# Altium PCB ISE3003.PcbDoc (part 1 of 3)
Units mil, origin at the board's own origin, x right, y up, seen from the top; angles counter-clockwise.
Board outline 3937.01 x 3937.01 mil, 2 copper layers (Top Layer, Bottom Layer), stack 62 mil thick; 230 components, 119 nets, 522 pads, 174 vias.
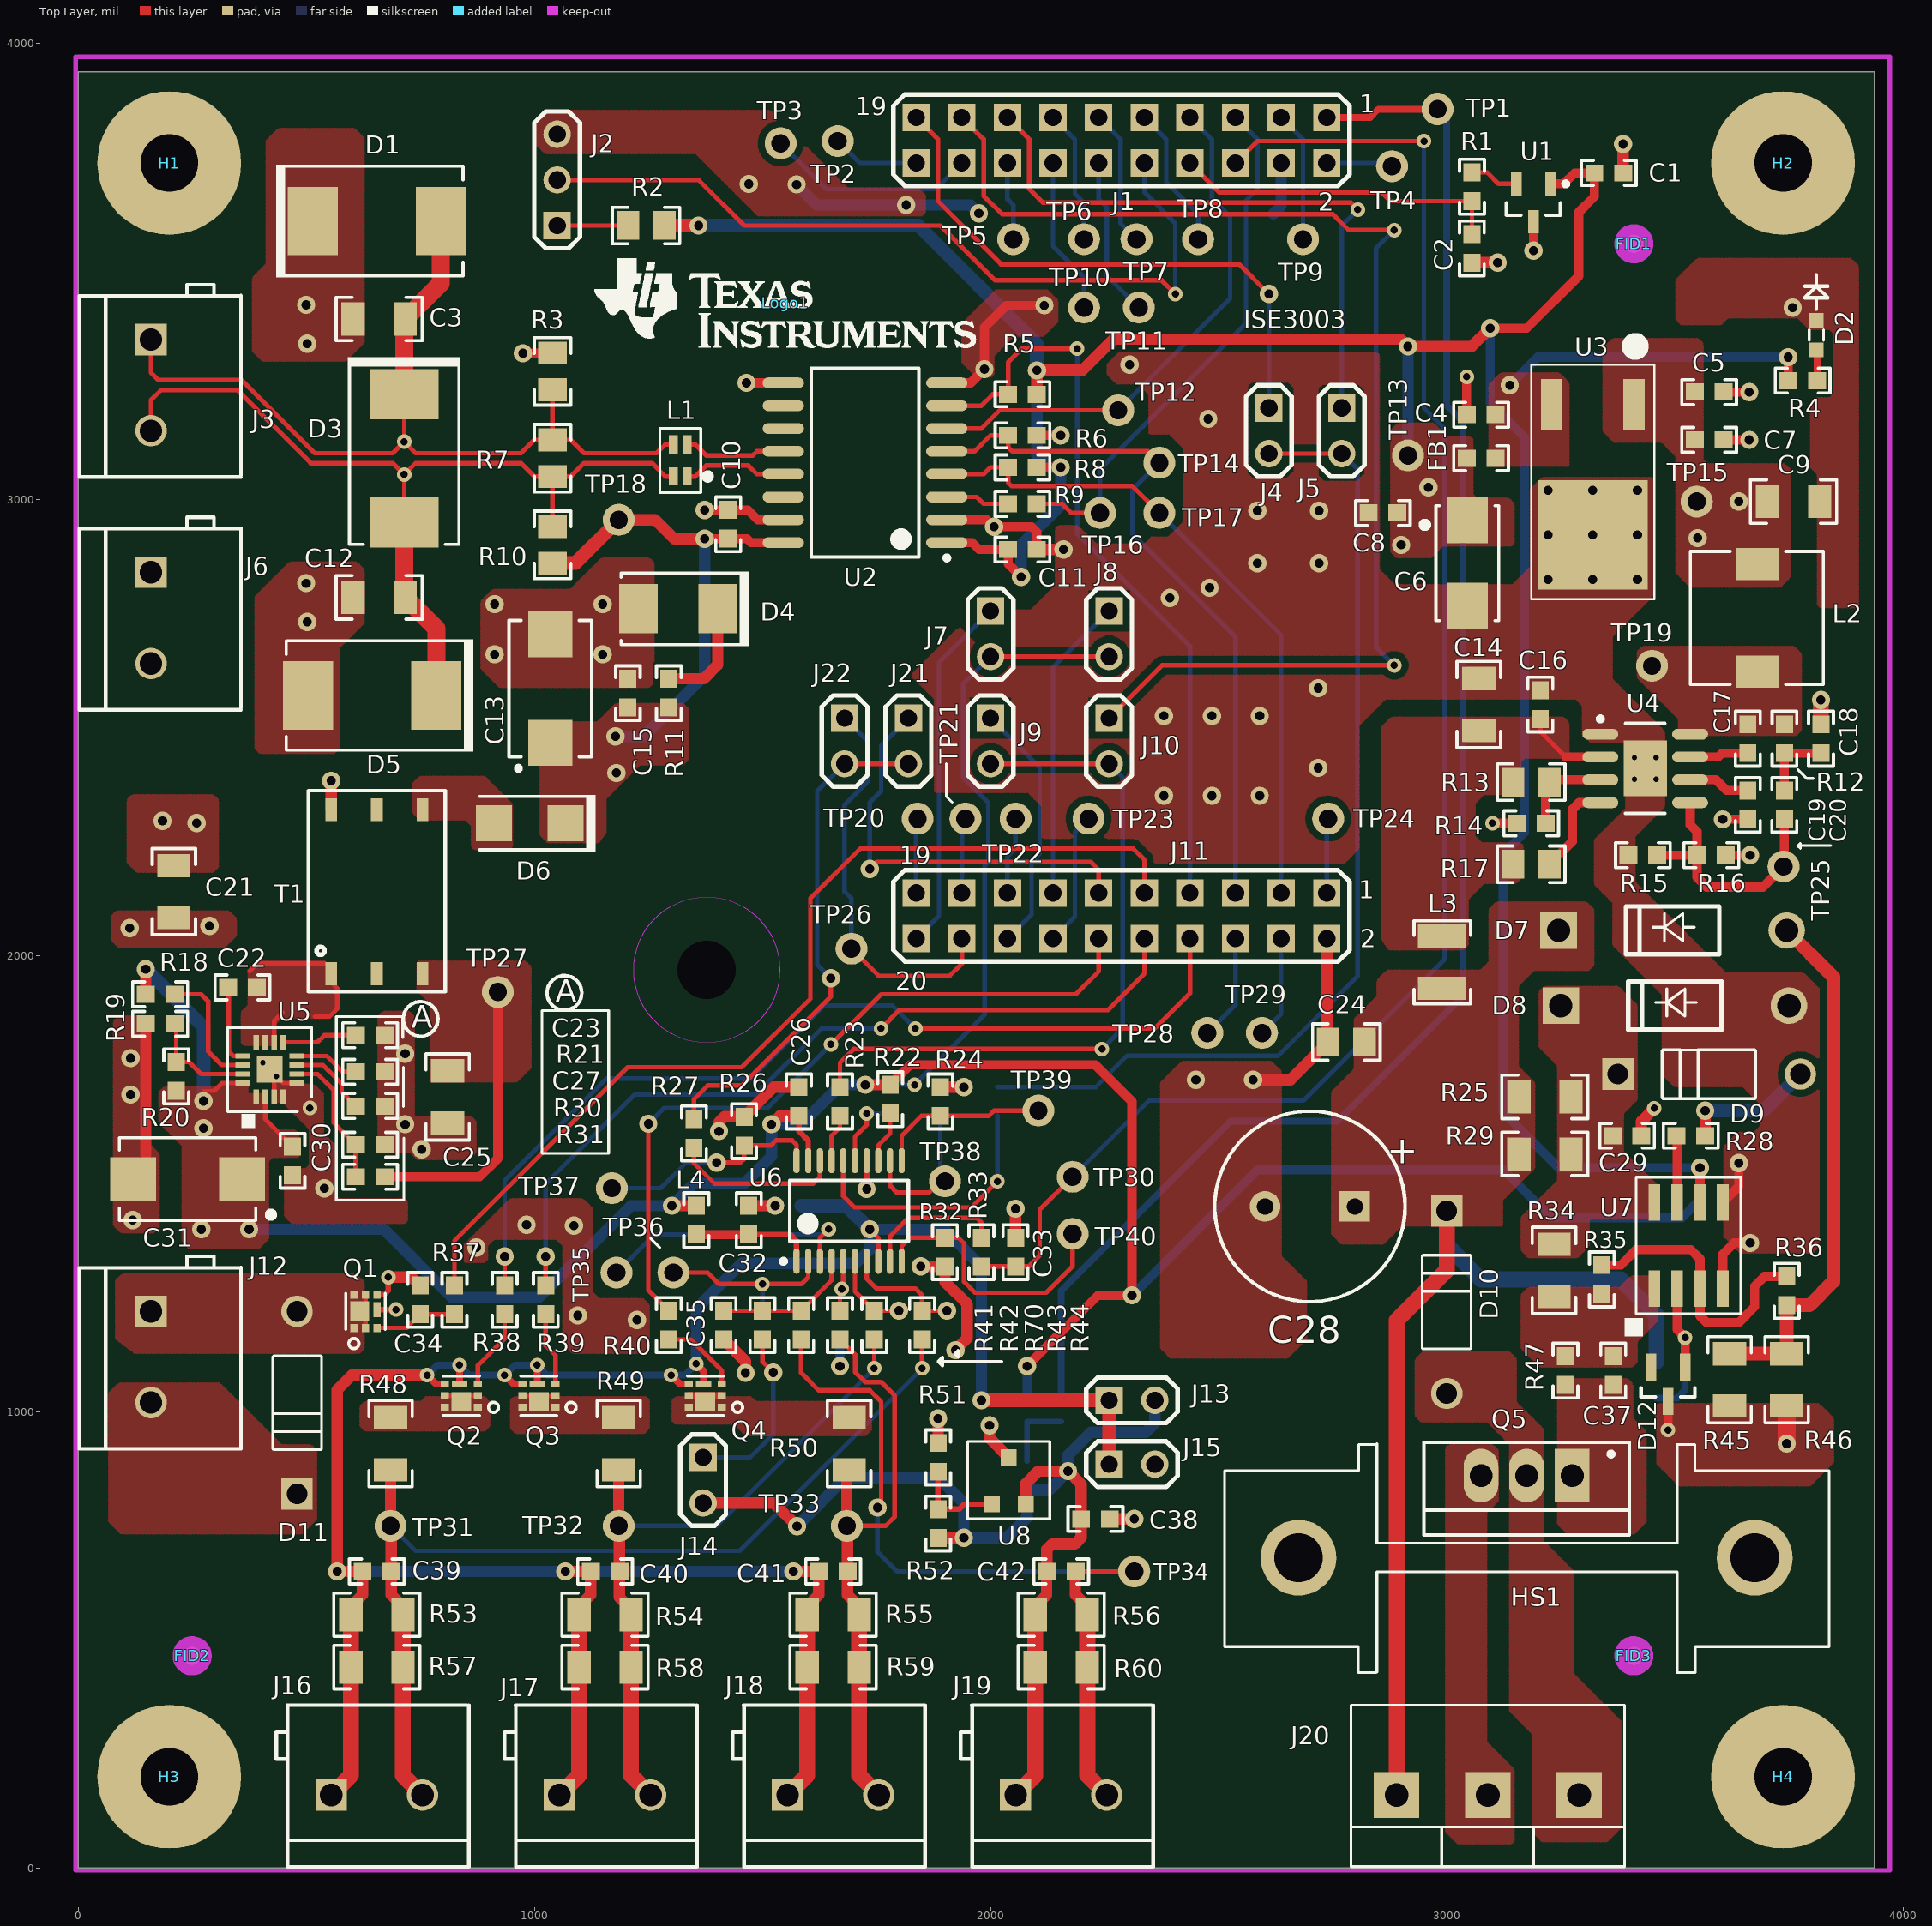
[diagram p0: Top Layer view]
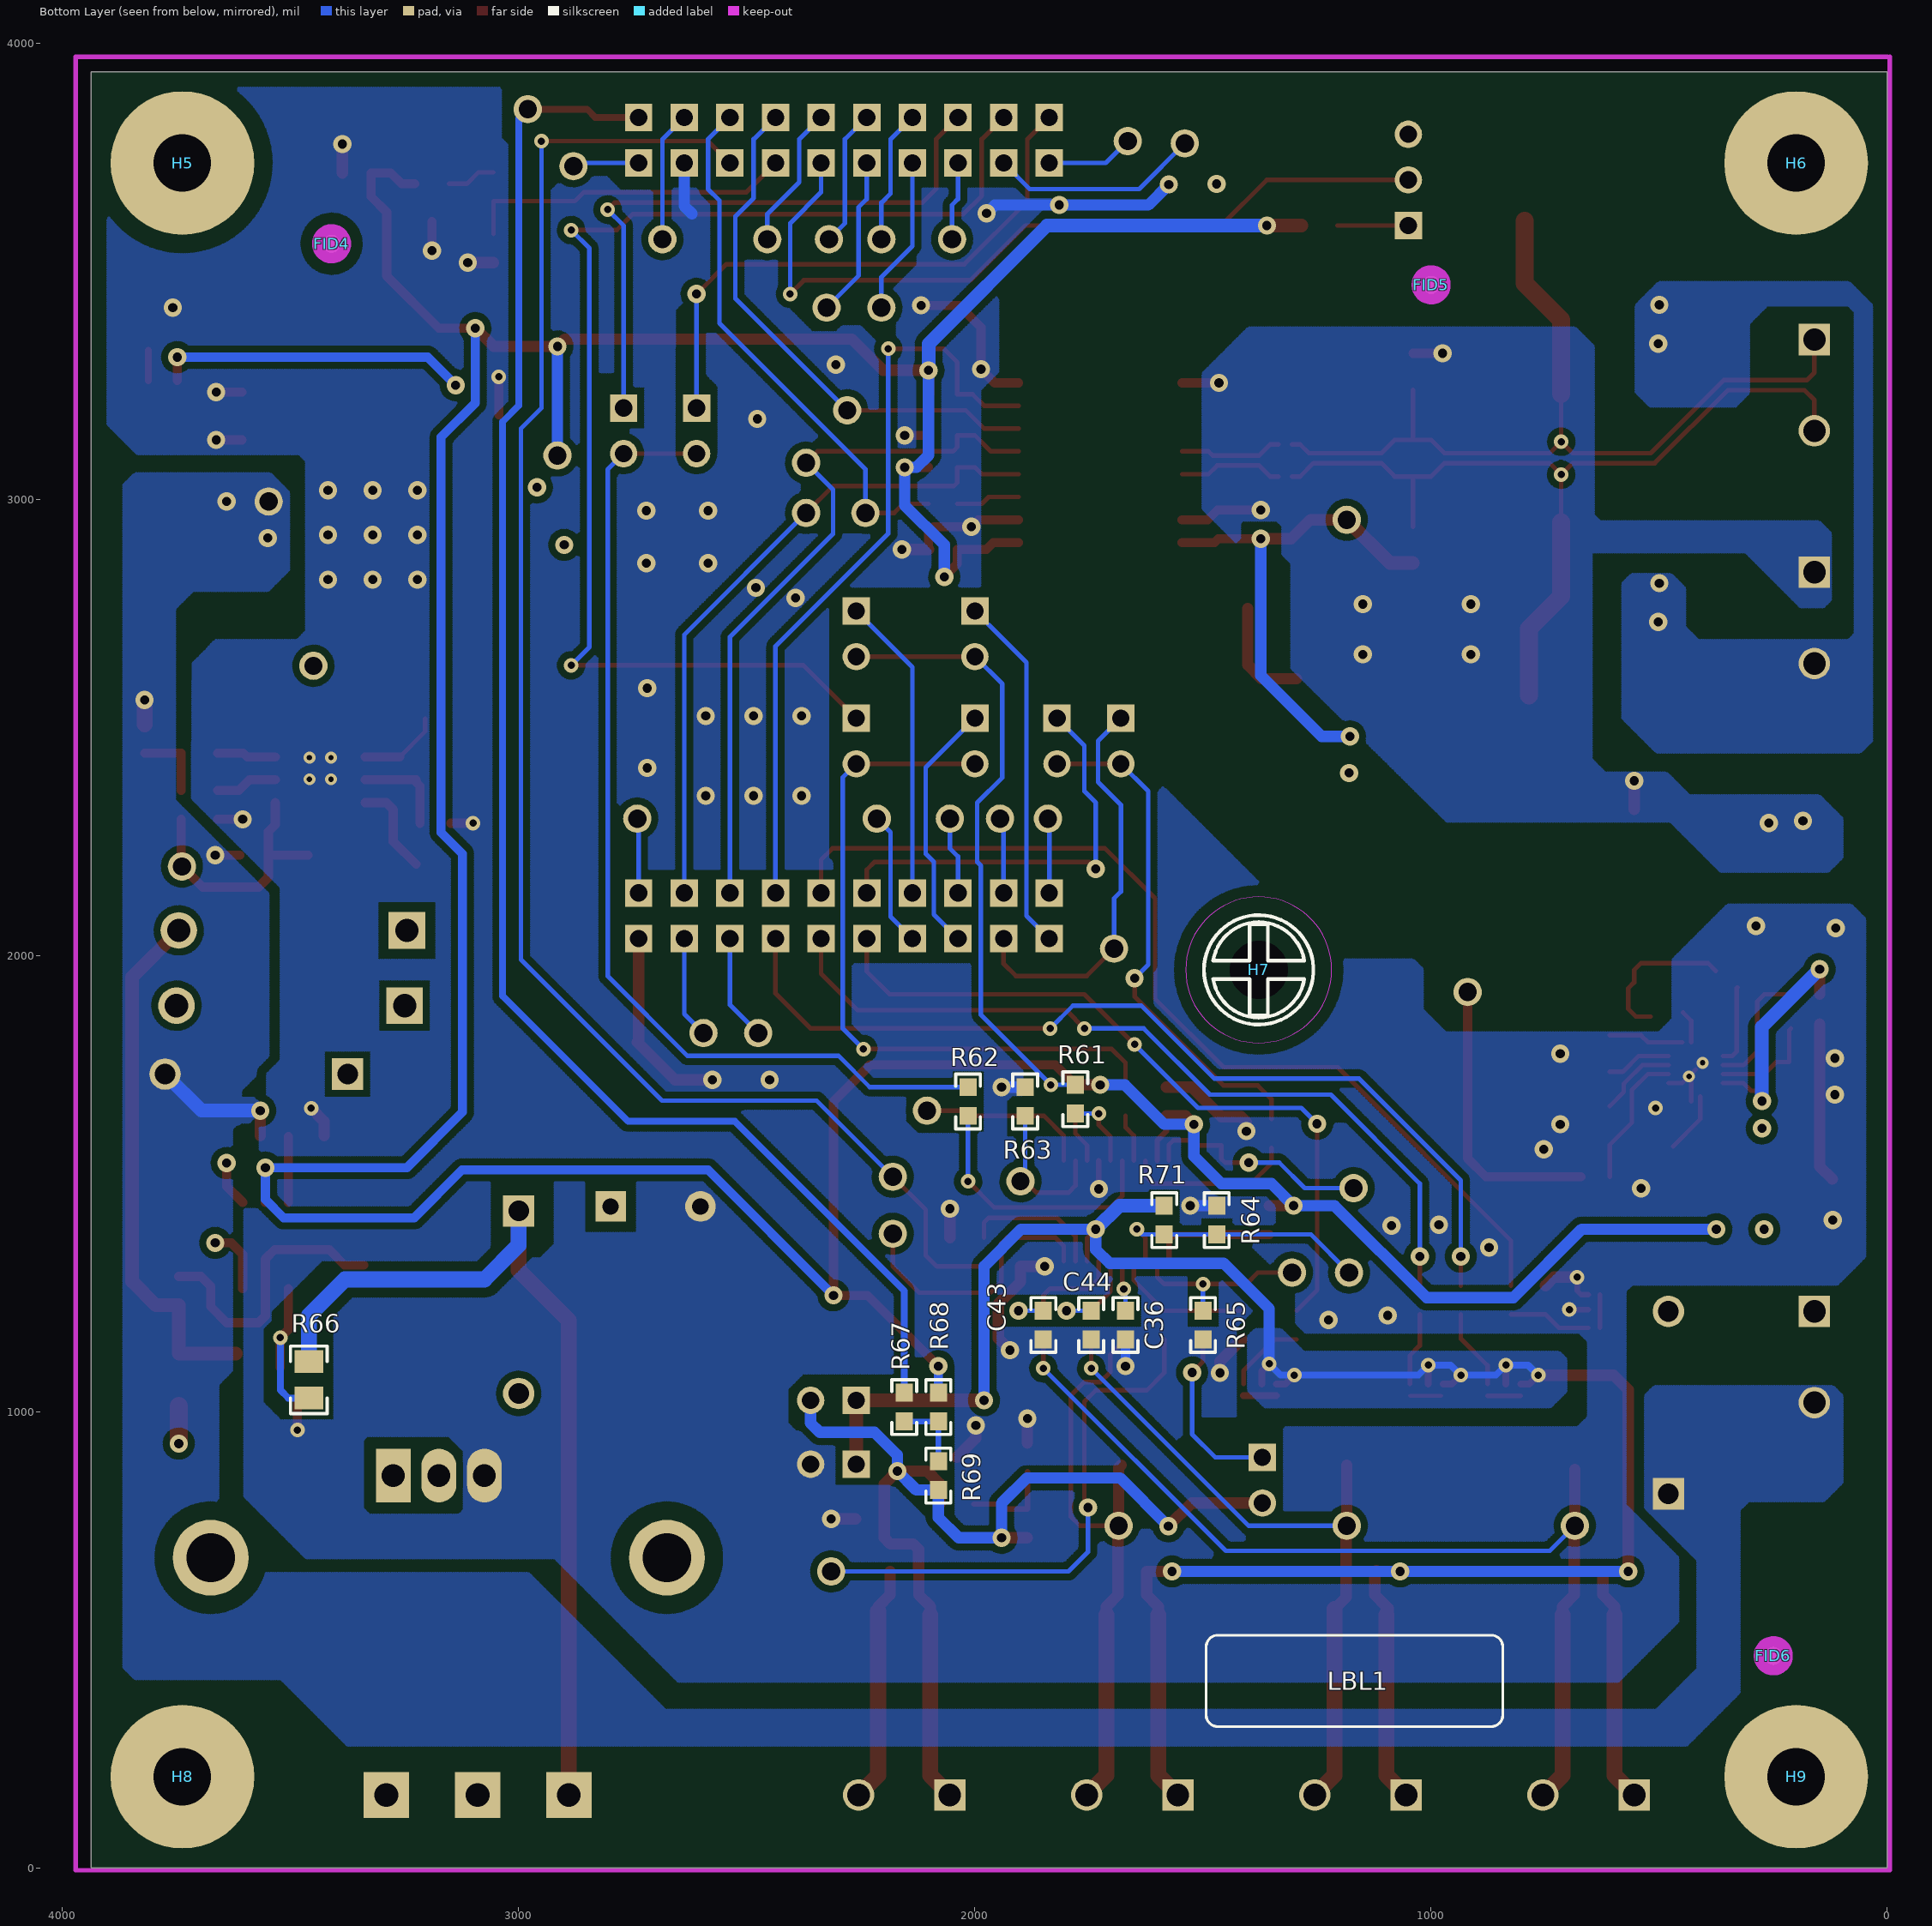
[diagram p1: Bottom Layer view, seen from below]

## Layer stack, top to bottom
Top Layer: signal copper 1.4
Dielectric: core 59.2, FR-4, Dk 4.8
Bottom Layer: signal copper 1.4

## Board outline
0,0 0,3937.01 3937.01,3937.01 3937.01,0

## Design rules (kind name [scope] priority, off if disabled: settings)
AcuteAngle [All] p1: minimum=4.50000000000000E+0001 checktracksonly=FALSE
AssemblyTestPointUsage [All] p1: valid=2
Clearance Clearance_MTG [InPadClass('MTG') vs InPolygon] p1: gap=40
Clearance Clearance_39V [InNet('39V')] p2: gap=22
Clearance Clearance_THPIN [IsVia vs IsThruPin] p3: gap=12
Clearance "Clearance_PAD Class" [InPadClass('PADClass') vs InPadClass('PADClass')] p4: gap=7.9
Clearance "Via to Via" [IsVia vs IsVia] p5: gap=12
Clearance "Via to SMT PIN" [IsVia vs IsSMTPin] p6: gap=12
Clearance "Clearance_Poly to Poly" [InPolygon vs InPolygon] p7: gap=20
Clearance Clearance_BoardEdge_MountingHoles [OnCopper and InComponentClass('Mounting Holes') vs IsKeepOut] p8: gap=40
Clearance Clearance_BoardEdge_Poly [OnCopper and InPoly vs IsKeepOut] p9: gap=25
Clearance Clearance_BoardEdge [OnCopper and Not InComponentClass('Logo') and not InComponentClass('FiducialMark') and not InRegion(1000,500,4000,800) and Not IsKeepout vs IsKeepOut] p10: gap=40
Clearance Clearance_Poly [InPolygon] p11: gap=15
Clearance [All] p12: gap=8
ComponentClearance ComponentClearance_Logo [InComponentClass('Logo')] p1: gap=50 collisioncheckmode=3 verticalgap=10 showdistances=FALSE
ComponentClearance ComponentClearance_ScrewToNut [(HasFootprint('NY PMS 440 0025 PH')) vs (HasFootprint('Keystone_1902C'))] p2: gap=5 collisioncheckmode=3 verticalgap=10 showdistances=FALSE
ComponentClearance ComponentClearance_MountingHoles [InComponentClass('Mounting Holes')] p3: gap=250 collisioncheckmode=3 verticalgap=100000 showdistances=FALSE
ComponentClearance ComponentClearance_SmallPassives [HasFootprint('0201*') or HasFootprint('0402*') or HasFootprint('0508') or HasFootprint('0603*') or HasFootprint('0612') or HasFootprint('0805*') or HasFootprint('0815*') or HasFootprint('0830*') or HasFootprint('1206*') or HasFootprint('1210*') or HasFootprint('1808*') or HasFootprint('1812*') or HasFootprint('1825*') or HasFootprint('2010*') or HasFootprint('2220*') or HasFootprint('2225*') or HasFootprint('2512*') or HasFootprint('2728*') or HasFootprint('3518*') vs HasFootprint('0201*') or HasFootprint('0402*') or HasFootprint('0508') or HasFootprint('0603*') or HasFootprint('0612') or HasFootprint('0805*') or HasFootprint('0815*') or HasFootprint('0830*') or HasFootprint('1206*') or HasFootprint('1210*') or HasFootprint('1808*') or HasFootprint('1812*') or HasFootprint('1825*') or HasFootprint('2010*') or HasFootprint('2220*') or HasFootprint('2225*') or HasFootprint('2512*') or HasFootprint('2728*') or HasFootprint('3518*')] p4: gap=20 collisioncheckmode=3 verticalgap=10 showdistances=FALSE
ComponentClearance ComponentClearance_THtoSMT [IsThruComponent vs IsSMTComponent] p5: gap=100 collisioncheckmode=3 verticalgap=30 showdistances=FALSE
ComponentClearance ComponentClearance_THtoTH [IsThruComponent vs IsThruComponent] p6: gap=118.11 collisioncheckmode=3 verticalgap=30 showdistances=FALSE
ComponentClearance [All] p7: gap=40 collisioncheckmode=3 verticalgap=10 showdistances=FALSE
DiffPairsRouting DiffPair_DiffPairsRouting [InDifferentialPair ('RS485_2')] p1: maxlimit=12 minlimit=12 mostfreqgap=12 maxuncoupledlength=500
DiffPairsRouting DiffPair_RS485DiffPairsRouting [InDifferentialPair ('NewDifferentialPair1')] p2: maxlimit=12 minlimit=12 mostfreqgap=12 maxuncoupledlength=500
DiffPairsRouting DiffPair_RS485_2DiffPairsRouting [InDifferentialPair ('RS485_2')] p3: maxlimit=12 minlimit=12 mostfreqgap=12 maxuncoupledlength=500
DiffPairsRouting DiffPair_RS485_1DiffPairsRouting [InDifferentialPair ('RS485_1')] p4: maxlimit=12 minlimit=12 mostfreqgap=12 maxuncoupledlength=500
DiffPairsRouting [All] p5: maxlimit=100 minlimit=10 mostfreqgap=10 maxuncoupledlength=1000
FabricationTestPointUsage TestPointUsage [All] p1: valid=2 allowmultiple=FALSE
FabricationTestpoint Testpoint [All] p1: side=3 testpointundercomponent=TRUE minsize=40 maxsize=100 preferedsize=60 minholesize=0 maxholesize=40 preferedholesize=32 testpointgrid=1 allowsidetop=TRUE allowsidebottom=TRUE usegrid=TRUE gridtolerance=0.01
FanoutControl Fanout_LCC [IsLCC] p1: bgadir=Out bgaviamode=Centered fanoutstyle=Auto fanoutdirection=Alternating viagrid=1 // Fanout_LCC (Default Rule)
FanoutControl Fanout_BGA [IsBGA] p2: bgadir=Out bgaviamode=Centered fanoutstyle=Auto fanoutdirection=Alternating viagrid=1 // Fanout_BGA (Default Rule)
FanoutControl Fanout_Default [All] p4: bgadir=Out bgaviamode=Centered fanoutstyle=Auto fanoutdirection=Alternating viagrid=1 // Fanout_Default (Default Rule)
FanoutControl Fanout_Small [(CompPinCount < 5)] p5: bgadir=Out bgaviamode=Centered fanoutstyle=Auto fanoutdirection=OutThenIn viagrid=1 // Fanout_Small (Default Rule)
HoleSize [All] p1: absolutevalues=TRUE maxlimit=251 minlimit=8 maxpercent=80.000 minpercent=20.000
MatchedLengths DiffPair_MatchedLengths [InDifferentialPair ('RS485_2')] p1: tolerance=1000 checknetsindiffpair=TRUE checkdiffpairvsdiffpair=TRUE checkothers=TRUE
MatchedLengths DiffPair_RS485MatchedLengths [InDifferentialPair ('NewDifferentialPair1')] p2: tolerance=1000 checknetsindiffpair=TRUE checkdiffpairvsdiffpair=TRUE checkothers=TRUE
MatchedLengths DiffPair_RS485_2MatchedLengths [InDifferentialPair ('RS485_2')] p3: tolerance=1000 checknetsindiffpair=TRUE checkdiffpairvsdiffpair=TRUE checkothers=TRUE
MatchedLengths DiffPair_RS485_1MatchedLengths [InDifferentialPair ('RS485_1')] p4: tolerance=1000 checknetsindiffpair=TRUE checkdiffpairvsdiffpair=TRUE checkothers=TRUE
MinimumAnnularRing MinimumAnnularRing_ThermalPadVias [IsVia and InAnyComponent] p1: minimumring=5.91
MinimumAnnularRing [All] p2: minimumring=7
MinimumSolderMaskSliver MinimumSolderMaskSliver_Logo [InComponentClass('Logo') vs InComponentClass('Logo')] p1: minsoldermaskwidth=0.7
MinimumSolderMaskSliver [All] p2: minsoldermaskwidth=3.94
PlaneConnect [All] p1: planeconnectstyle=Relief reliefexpansion=10 reliefentries=4 reliefconductorwidth=10 reliefairgap=10
PolygonConnect PolygonConnect_All [All] p1: connectstyle=Direct reliefconductorwidth=10 reliefentries=4 polygonreliefangle="90 Angle" airgapwidth=10
RoutingVias ThermalPadVias [IsVia and InAnyComponent] p1: holewidth=7.87 width=19.68 viastyle="Through Hole" minholewidth=7.87 minwidth=19.68 maxholewidth=12 maxwidth=26
RoutingVias [All] p2: holewidth=16 width=32 viastyle="Through Hole" minholewidth=12 minwidth=26 maxholewidth=20 maxwidth=40
SMDToCorner [All] p1: distance=30000
SilkToSilkClearance [All] p1: silktosilkclearance=5
SilkscreenOverComponentPads [All] p1: minsilkscreentomaskgap=5
SolderMaskExpansion [All] p1: expansion=2
Width DiffPair_Width [InDifferentialPair('RS485_2')] p1: maxlimit=10 minlimit=10 preferedwidth=10
Width DiffPair_RS485Width [InDifferentialPair('NewDifferentialPair1')] p2: maxlimit=200 minlimit=10 preferedwidth=10
Width DiffPair_RS485_2Width [InDifferentialPair('RS485_2')] p3: maxlimit=100 minlimit=10 preferedwidth=10
Width DiffPair_RS485_1Width [InDifferentialPair('RS485_1')] p4: maxlimit=100 minlimit=10 preferedwidth=10
Width Width_RS485 [InNetClass('RS485')] p5: maxlimit=100 minlimit=10 preferedwidth=10
Width [All] p6: maxlimit=100 minlimit=6 preferedwidth=10 checkconnectedcopper=TRUE
14 further rules are at their usual default settings.

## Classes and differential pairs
pad class MTG: H1-1 H2-1 H3-1 H4-1 HS1-1 HS1-2
component class "Mounting Holes": H1 H2 H3 H4
component class Logo: Logo1
component class "Pg7 Hardware": FID1 FID2 FID3 FID4 FID5 FID6 H1 H2 H3 H4 H5 H6 H7 H8 H9 LBL1 Logo1 ZZ1 ZZ2 ZZ3 ZZ4
component class FiducialMark: FID1 FID2 FID3 FID4 FID5 FID6
component class AssemblyNote: ZZ1 ZZ2 ZZ3 ZZ4
component class Label: LBL1
component class Pg3: C4 C5 C6 C7 C8 C9 C14 C16 C17 C18 C19 C20 C24 C28 C29 C34 C37 D2 D7 D8 D9 D10 D11 D12 FB1 HS1 J12 J20 L2 L3 Q1 Q5 R4 R12 R13 R14 R15 R16 R17 R25 R28 R29 R34 R35 R36 R37 R45 R46 R47 R66 TP13 TP15 TP19 TP25 U3 U4 U7
component class Pg4: C1 C2 C26 C32 C33 C35 C36 C38 C39 C40 C41 C42 C43 C44 J13 J14 J15 J16 J17 J18 J19 L4 Q2 Q3 Q4 R1 R22 R23 R24 R26 R27 R32 R33 R38 R39 R40 R41 R42 R43 R44 R48 R49 R50 R51 R52 R53 R54 R55 R56 R57 R58 R59 R60 R61 R62 R63 R64 R65 R67 R68 R69 R70 R71 TP30 TP31 TP32 TP33 TP34 TP35 TP36 TP37 TP38 TP39 TP40 U1 U6 U8
component class Pg5: C3 C10 C11 C12 C13 C15 C21 C22 C23 C25 C27 C30 C31 D1 D3 D4 D5 D6 J3 J6 L1 R3 R5 R6 R7 R8 R9 R10 R11 R18 R19 R20 R21 R30 R31 T1 TP12 TP14 TP16 TP17 TP18 TP27 U2 U5
component class Pg6: J1 J2 J4 J5 J7 J8 J9 J10 J11 J21 J22 R2 TP1 TP2 TP3 TP4 TP5 TP6 TP7 TP8 TP9 TP10 TP11 TP20 TP21 TP22 TP23 TP24 TP26 TP28 TP29
pad class PADClass: U5-1 U5-2 U5-3 U5-4 U5-5 U5-6 U5-7 U5-8 U5-9 U5-10 U5-11 U5-12 U5-13 U5-14 U5-15 U5-16
differential pair RS485_2: +NetL1_2 -NetL1_1
differential pair RS485_1: +RS485_ISO_A -RS485_ISO_B

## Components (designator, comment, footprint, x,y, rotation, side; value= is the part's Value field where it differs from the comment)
C1 "06033C104JAT2A" 0603 3355,3715 r0 top (schematic designator C47)
C2 "06033C104JAT2A" 0603 3055,3550 r90 top (schematic designator C17)
C3 "CC1206KKX7RCBB102" 1206 660,3395 r180 top (schematic designator C32)
C4 "C1608X7R1C105K" 0603 3075,3185 r180 top (schematic designator C13)
C5 "C0603C104K5RACTU" 0603 3575,3235 r0 top (schematic designator C15)
C6 "293D475X9035C2TE3" 6032-28 3045,2860 r270 top (schematic designator C11)
C7 "C1608X7R1C105K" 0603 3575,3130 r0 top (schematic designator C14)
C8 "C0603C104K5RACTU" 0603 2860,2970 r180 top (schematic designator C12)
C9 "GRM31CR61C226KE15L" 1206 3760,2995 r0 top (schematic designator C8)
C10 "06033C104JAT2A" 0603 1425,2945 r270 top (schematic designator C30)
C11 "06033C104JAT2A" 0603 2070,2890 r180 top (schematic designator C29)
C12 "CC1206KKX7RCBB102" 1206 660,2785 r0 top (schematic designator C31)
C13 "T495X476K035ATE300" 7343-43 1035,2585 r90 top (schematic designator C38)
C14 "GRM31CR72A105KA01L" 1206 3070,2550 r270 top (schematic designator C1)
C15 "06033C104JAT2A" 0603 1205,2575 r90 top (schematic designator C39)
C16 "06033C104JAT2A" 0603 3205,2550 r90 top (schematic designator C2)
C17 "C1608C0G1E103J" 0603 3660,2475 r90 top (schematic designator C6)
C18 "C0603C332K5RACTU" 0603 3820,2475 r270 top (schematic designator C7)
C19 "C1608X5R1E105K080AC" 0603 3660,2330 r270 top (schematic designator C10)
C20 "06033C104JAT2A" 0603 3740,2330 r90 top (schematic designator C9)
C21 "CC1206KKX7RCBB102" 1206 210,2140 r270 top (schematic designator C36)
C22 "06033C104JAT2A" 0603 360,1930 r180 top (schematic designator C33)
C23 "06033C104JAT2A" 0603 640,1825 r180 top (schematic designator C37)
C24 "C0805C104K1RACTU" 0805_HV 2780,1810 r180 top (schematic designator C4)
C25 "1206YD226MAT2A" 1206 810,1690 r270 top (schematic designator C41)
C26 "06033C104JAT2A" 0603 1580,1680 r270 top (schematic designator C19)
C27 "C1608C0G1E103J" 0603 640,1670 r0 top (schematic designator C40)
C28 "100YXJ100M10X20" YXJ_1000x2000 2700,1450 r180 top locked (schematic designator C3)
C29 "C0603C104K5RACTU" 0603 3395,1605 r0 top (schematic designator C45)
C30 "06033C104JAT2A" 0603 470,1550 r270 top (schematic designator C35)
C31 "T495X476K035ATE300" 7343-43 240,1510 r180 top (schematic designator C34)
C32 "06033C104JAT2A" 0603 1470,1420 r270 top (schematic designator C20)
C33 "C1608C0G1E103J" 0603 2055,1350 r90 top (schematic designator C27)
C34 "06033C104JAT2A" 0603 750,1245 r90 top (schematic designator C16)
C35 "C1608C0G1E103J" 0603 1415,1190 r270 top (schematic designator C23)
C36 "C1608C0G1E103J" 0603 1670,1190 r270 bottom (schematic designator C24)
C37 "06033C104JAT2A" 0603 3365,1090 r270 top (schematic designator C5)
C38 "06033C104JAT2A" 0603 2230,765 r180 top (schematic designator C46)
C39 "06033C101KAT2A" 0603 655,650 r180 top (schematic designator C18)
C40 "06033C101KAT2A" 0603 1155,650 r180 top (schematic designator C21)
C41 "06033C101KAT2A" 0603 1655,650 r180 top (schematic designator C22)
C42 "06033C101KAT2A" 0603 2155,650 r180 top (schematic designator C28)
C43 "C1608C0G1E103J" 0603 1850,1190 r270 bottom (schematic designator C26)
C44 "C1608C0G1E103J" 0603 1745,1190 r270 bottom (schematic designator C25)
D1 "SMCJ15CA" SMC 655,3610 r0 top (schematic designator D8)
D2 "LED_LG L29K-G2J1-24-Z" LED0603AA 3810,3360 r270 top (schematic designator D4)
D3 "SMCJ15CA" SMC 715,3090 r270 top (schematic designator D7)
D4 "SMBJ5338B-TP" SMB 1315,2760 r180 top (schematic designator D10)
D5 "SMCJ15CA" SMC 645,2570 r180 top (schematic designator D6)
D6 "B120-13-F" SMA 990,2290 r180 top (schematic designator D9)
D7 "1N4754A-TP" DO-41#1 3245,2055 r0 top (schematic designator D2)
D8 "1N4745A-TP" DO-41#1 3250,1890 r0 top (schematic designator D11)
D9 "1N4007" DO-41#2 3575,1740 r0 top (schematic designator D12)
D10 "1N4007" DO-41#2 3000,1240 r270 top (schematic designator D1)
D11 "1N4007" DO-41#2 480,1020 r90 top (schematic designator D5)
D12 "BAS21-7-F" SOT-23#1 3485,1060 r270 top (schematic designator D3)
FB1 "1000 OHM" 0603 3075,3090 r180 top
FID1 "Fiducial" Fiducial10-20 3410,3560 r0 top
FID2 "Fiducial" Fiducial10-20 250,465 r0 top
FID3 "Fiducial" Fiducial10-20 3410,465 r0 top
FID4 "Fiducial" Fiducial10-20 3410,3560 r90 bottom
FID5 "Fiducial" Fiducial10-20 1000,3470 r90 bottom
FID6 "Fiducial" Fiducial10-20 250,465 r90 bottom
H1 "NY PMS 440 0025 PH" "NY PMS 440 0025 PH" 200,3737.01 r0 top locked
H2 "NY PMS 440 0025 PH" "NY PMS 440 0025 PH" 3737.01,3737.01 r0 top locked
H3 "NY PMS 440 0025 PH" "NY PMS 440 0025 PH" 200,200 r0 top locked
H4 "NY PMS 440 0025 PH" "NY PMS 440 0025 PH" 3737.01,200 r0 top locked
H5 "1902C" Keystone_1902C 3737.01,3737.01 r180 bottom locked (schematic designator H6)
H6 "1902C" Keystone_1902C 200,3737.01 r180 bottom locked (schematic designator H5)
H7 "MH 3.2MM" MH3.2_H5_W6_KO8_STARHEAD 1377.95,1968.5 r180 bottom locked (schematic designator H9)
H8 "1902C" Keystone_1902C 3737.01,200 r180 bottom locked
H9 "1902C" Keystone_1902C 200,200 r180 bottom locked (schematic designator H7)
HS1 "HEATSINK_513201" HEATSINK_513201 3175,680 r180 top locked
J1 "HEADER_2X10" HEADER_2X10P 2737.01,3837.01 r180 top locked (schematic designator J12)
J2 "JUMPER_3X100MIL" HDR100_1X3 1050,3600 r90 top (schematic designator J20)
J3 "ED120/2DS" CONN_ED120-2DS 160,3250 r180 top locked (schematic designator J11)
J4 "JUMPER_2X100MIL" HDR100_1X2 2610,3200 r270 top (schematic designator J18)
J5 "JUMPER_2X100MIL" HDR100_1X2 2770,3200 r270 top (schematic designator J19)
J6 "ED120/2DS" CONN_ED120-2DS 160,2740 r180 top (schematic designator J10)
J7 "JUMPER_2X100MIL" HDR100_1X2 2000,2755 r270 top (schematic designator J15)
J8 "JUMPER_2X100MIL" HDR100_1X2 2260,2755 r270 top (schematic designator J14)
J9 "JUMPER_2X100MIL" HDR100_1X2 2000,2520 r270 top (schematic designator J17)
J10 "JUMPER_2X100MIL" HDR100_1X2 2260,2520 r270 top (schematic designator J16)
J11 "HEADER_2X10" HEADER_2X10P 2737.01,2137.01 r180 top locked (schematic designator J13)
J12 "ED120/2DS" CONN_ED120-2DS 160,1120 r180 top locked (schematic designator J2)
J13 "JUMPER_2X100MIL" HDR100_1X2 2260,1025 r0 top (schematic designator J8)
J14 "JUMPER_2X100MIL" HDR100_1X2 1370,900 r270 top (schematic designator J21)
J15 "JUMPER_2X100MIL" HDR100_1X2 2260,885 r0 top (schematic designator J9)
J16 "ED120/2DS" CONN_ED120-2DS 655,160 r270 top locked (schematic designator J3)
J17 "ED120/2DS" CONN_ED120-2DS 1155,160 r270 top locked (schematic designator J4)
J18 "ED120/2DS" CONN_ED120-2DS 1655,160 r270 top locked (schematic designator J5)
J19 "ED120/2DS" CONN_ED120-2DS 2155,160 r270 top locked (schematic designator J7)
J20 "TBLK_15A_3X5.1MM" TB_3X5.1MM 2890,160 r0 top locked (schematic designator J1)
J21 "JUMPER_2X100MIL" HDR100_1X2 1820,2520 r270 top
J22 "JUMPER_2X100MIL" HDR100_1X2 1680,2520 r270 top
L1 "ACM2012-900-2P-T002" IND_0805-4P 1320,3085 r90 top (schematic designator L4)
L2 "SRR7032-221M" SRR7045 3680,2740 r90 top
L3 "B82422H1332K" 1210 2990,1985 r90 top (schematic designator L1)
L4 "BLM18SG331TN1D" 0603 1355,1420 r90 top (schematic designator L3)
LBL1 "Size: 0.65\" x 0.20 \"" Label_650x200 1168,410 r180 bottom
Logo1 "Texas Instruments" TI_Stacked_SolderMask_Small 1550,3430 r0 top
Q1 "CSD17571Q2" SON_CSD17571Q2 630,1220 r0 top (schematic designator Q2)
Q2 "CSD17571Q2" SON_CSD17571Q2 840,1035 r90 top (schematic designator Q3)
Q3 "CSD17571Q2" SON_CSD17571Q2 1010,1035 r90 top (schematic designator Q4)
Q4 "CSD17571Q2" SON_CSD17571Q2 1375,1035 r90 top (schematic designator Q5)
Q5 "CSD18537NKCS" TO-220AB 3175,860 r180 top
R1 "CRCW0603100RFKEA" 0603 3055,3685 r270 top (schematic designator R14)
R2 "CRCW08051K00FKEA" 0805_HV 1245,3600 r0 top (schematic designator R67)
R3 "CRCW0805470RFKEA" 0805_HV 1040,3280 r270 top (schematic designator R44)
R4 "CRCW0603300RJNEA" 0603 3780,3260 r180 top (schematic designator R12)
R5 "CRCW060310K0JNEA" 0603 2070,3230 r0 top (schematic designator R40)
R6 "CRCW060310K0JNEA" 0603 2070,3140 r180 top (schematic designator R45)
R7 "CRCW0805120RJNEA" 0805_HV 1040,3090 r270 top (schematic designator R43)
R8 "CRCW060310K0JNEA" 0603 2070,3070 r0 top (schematic designator R41)
R9 "CRCW060310R0FKEA" 0603 2070,2990 r180 top (schematic designator R42)
R10 "CRCW0805470RFKEA" 0805_HV 1040,2900 r270 top (schematic designator R39)
R11 "CRCW0603200RFKEA" 0603 1295,2575 r270 top (schematic designator R49)
R12 "CRCW060363K4FKEA" 0603 3740,2475 r270 top (schematic designator R6)
R13 "RT0805BRD07121KL" 0805_HV 3185,2380 r180 top (schematic designator R7)
R14 "CRCW060310K0FKEA" 0603 3185,2290 r0 top (schematic designator R11)
R15 "RC0603FR-071KL" 0603 3430,2220 r0 top (schematic designator R10)
R16 "CRCW06039K76FKEA" 0603 3580,2220 r0 top (schematic designator R8)
R17 "RG2012P-5362-B-T5" 0805_HV 3185,2200 r180 top (schematic designator R3)
R18 "CRCW0603100KFKEA" 0603 180,1915 r180 top (schematic designator R46)
R19 "CRCW060321K5FKEA" 0603 180,1850 r0 top (schematic designator R48)
R20 "CRCW060330K0JNEA" 0603 215,1735 r270 top (schematic designator R47)
R21 "CRCW0603280KFKEA" 0603 640,1745 r180 top (schematic designator R52)
R22 "CRCW060310K0FKEA" 0603 1780,1685 r270 top (schematic designator R36)
R23 "CRCW060310R0JNEA" 0603 1670,1680 r90 top (schematic designator R25)
R24 "CRCW06030000Z0EA" 0603 1890,1680 r270 top (schematic designator R34)
R25 "CRCW120610K0FKEA" 1206 3215,1690 r180 top (schematic designator R65)
R26 "CRCW06030000Z0EA" 0603 1460,1615 r270 top (schematic designator R31)
R27 "CRCW060310R0JNEA" 0603 1350,1610 r90 top (schematic designator R23)
R28 "CRCW060310K0FKEA" 0603 3535,1605 r0 top (schematic designator R53)
R29 "CRCW120610K0FKEA" 1206 3215,1565 r180 top (schematic designator R64)
R30 "CRCW060343K2FKEA" 0603 640,1585 r180 top (schematic designator R51)
R31 "CRCW0603100KFKEA" 0603 640,1515 r180 top (schematic designator R50)
R32 "CRCW06030000Z0EA" 0603 1900,1350 r90 top (schematic designator R33)
R33 "CRCW0603100RFKEA" 0603 1980,1350 r270 top (schematic designator R32)
R34 "CRCW120610K0FKEA" 1206 3235,1310 r270 top (schematic designator R66)
R35 "CRCW06031M00FKEA" 0603 3340,1290 r270 top (schematic designator R1)
R36 "RNCF0603TKY10K0" 0603 3745,1265 r270 top (schematic designator R4)
R37 "CRCW0603300RJNEA" 0603 825,1245 r270 top (schematic designator R13)
R38 "CRCW0603300RJNEA" 0603 935,1245 r270 top (schematic designator R57)
R39 "CRCW0603300RJNEA" 0603 1025,1245 r270 top (schematic designator R58)
R40 "CRCW0603300RJNEA" 0603 1295,1190 r270 top (schematic designator R59)
R41 "CRCW0603100RFKEA" 0603 1500,1190 r270 top (schematic designator R17)
R42 "CRCW06031K00JNEA" 0603 1585,1190 r90 top (schematic designator R24)
R43 "CRCW06031K00JNEA" 0603 1745,1190 r90 top (schematic designator R21)
R44 "CRCW06031K00JNEA" 0603 1850,1190 r90 top (schematic designator R20)
R45 "CRCW12061K00FKEA" 1206 3620,1070 r90 top (schematic designator R63)
R46 "CRCW12061K00FKEA" 1206 3745,1070 r90 top (schematic designator R9)
R47 "RG1608P-511-B-T5" 0603 3260,1090 r270 top (schematic designator R5)
R48 "CRCW120622R0JNEA" 1206 685,930 r90 top (schematic designator R60)
R49 "CRCW120622R0JNEA" 1206 1185,930 r90 top (schematic designator R61)
R50 "CRCW120622R0JNEA" 1206 1690,930 r90 top (schematic designator R62)
R51 "RNCF0603TKY10K0" 0603 1885,900 r270 top (schematic designator R56)
R52 "CRCW060330K0JNEA" 0603 1885,755 r270 top (schematic designator R55)
R53 "CRCW120622R0JNEA" 1206 655,555 r0 top (schematic designator R16)
R54 "CRCW120622R0JNEA" 1206 1155,555 r0 top (schematic designator R19)
R55 "CRCW120622R0JNEA" 1206 1655,555 r0 top (schematic designator R29)
R56 "CRCW120622R0JNEA" 1206 2155,555 r0 top (schematic designator R38)
R57 "CRCW120622R0JNEA" 1206 655,440 r0 top (schematic designator R15)
R58 "CRCW120622R0JNEA" 1206 1155,440 r0 top (schematic designator R18)
R59 "CRCW120622R0JNEA" 1206 1655,440 r0 top (schematic designator R28)
R60 "CRCW120622R0JNEA" 1206 2155,440 r0 top (schematic designator R37)
R61 "CRCW060310R0JNEA" 0603 1780,1685 r90 bottom (schematic designator R22)
R62 "CRCW060310R0JNEA" 0603 2015,1680 r90 bottom (schematic designator R27)
R63 "CRCW06030000Z0EA" 0603 1890,1680 r270 bottom (schematic designator R35)
R64 "CRCW06030000Z0EA" 0603 1470,1420 r270 bottom (schematic designator R26)
R65 "CRCW06030000Z0EA" 0603 1500,1190 r90 bottom (schematic designator R30)
R66 "ERJ-6GEYJ473V" 0805_HV 3460,1070 r90 bottom (schematic designator R2)
R67 "CRCW06030000Z0EA" 0603 2155,1010 r270 bottom (schematic designator R68)
R68 "CRCW0603100RFKEA" 0603 2080,1010 r270 bottom (schematic designator R69)
R69 "CRCW0603470RJNEA" 0603 2080,860 r90 bottom (schematic designator R54)
R70 "CRCW06031K00JNEA" 0603 1670,1190 r90 top
R71 "CRCW06030000Z0EA" 0603 1585,1420 r90 bottom
T1 "760390015" 760390015 555,1960 r90 top
TP1 "TP-040_RND" TP-040_RND 2980,3855 r90 top (schematic designator TP16)
TP2 "TP-040_RND" TP-040_RND 1665,3785 r90 top (schematic designator TP29)
TP3 "TP-040_RND" TP-040_RND 1540,3780 r90 top (schematic designator TP27)
TP4 "TP-040_RND" TP-040_RND 2880,3730 r90 top (schematic designator TP18)
TP5 "TP-040_RND" TP-040_RND 2050,3570 r90 top (schematic designator TP34)
TP6 "TP-040_RND" TP-040_RND 2205,3570 r90 top (schematic designator TP25)
TP7 "TP-040_RND" TP-040_RND 2320,3570 r90 top (schematic designator TP31)
TP8 "TP-040_RND" TP-040_RND 2455,3570 r90 top (schematic designator TP22)
TP9 "TP-040_RND" TP-040_RND 2685,3570 r90 top (schematic designator TP30)
TP10 "TP-040_RND" TP-040_RND 2205,3420 r90 top (schematic designator TP33)
TP11 "TP-040_RND" TP-040_RND 2325,3420 r90 top (schematic designator TP32)
TP12 "TP-040_RND" TP-040_RND 2280,3195 r90 top (schematic designator TP13)
TP13 "TP-040_RND" TP-040_RND 2915,3096 r0 top (schematic designator TP4)
TP14 "TP-040_RND" TP-040_RND 2370,3080 r90 top (schematic designator TP12)
TP15 "TP-040_RND" TP-040_RND 3548,2995 r0 top (schematic designator TP2)
TP16 "TP-040_RND" TP-040_RND 2240,2970 r90 top (schematic designator TP10)
TP17 "TP-040_RND" TP-040_RND 2370,2970 r90 top (schematic designator TP11)
TP18 "TP-040_RND" TP-040_RND 1185,2955 r90 top (schematic designator TP14)
TP19 "TP-040_RND" TP-040_RND 3450,2635 r0 top (schematic designator TP1)
TP20 "TP-040_RND" TP-040_RND 1840,2300 r90 top (schematic designator TP28)
TP21 "TP-040_RND" TP-040_RND 1945,2300 r90 top (schematic designator TP26)
TP22 "TP-040_RND" TP-040_RND 2055,2300 r90 top (schematic designator TP36)
TP23 "TP-040_RND" TP-040_RND 2215,2300 r90 top (schematic designator TP35)
TP24 "TP-040_RND" TP-040_RND 2740,2300 r90 top (schematic designator TP17)
TP25 "TP-040_RND" TP-040_RND 3738,2195 r0 top (schematic designator TP3)
TP26 "TP-040_RND" TP-040_RND 1695,2015 r90 top (schematic designator TP37)
TP27 "TP-040_RND" TP-040_RND 920,1920 r90 top (schematic designator TP15)
TP28 "TP-040_RND" TP-040_RND 2475,1830 r90 top (schematic designator TP20)
TP29 "TP-040_RND" TP-040_RND 2595,1830 r90 top (schematic designator TP19)
TP30 "TP-040_RND" TP-040_RND 2180,1515 r0 top (schematic designator TP8)
TP31 "TP-040_RND" TP-040_RND 685,750 r0 top (schematic designator TP5)
TP32 "TP-040_RND" TP-040_RND 1185,750 r0 top (schematic designator TP6)
TP33 "TP-040_RND" TP-040_RND 1685,750 r0 top (schematic designator TP7)
TP34 "TP-040_RND" TP-040_RND 2315,650 r0 top (schematic designator TP9)
TP35 "TP-040_RND" TP-040_RND 1180,1305 r90 top
TP36 "TP-040_RND" TP-040_RND 1305,1305 r90 top
TP37 "TP-040_RND" TP-040_RND 1170,1490 r90 top
TP38 "TP-040_RND" TP-040_RND 1900,1505 r90 top
TP39 "TP-040_RND" TP-040_RND 2105,1660 r90 top
TP40 "TP-040_RND" TP-040_RND 2180,1390 r90 top
U1 "LM62BIM3" MF03A_N 3190,3650 r270 top (schematic designator U4)
U2 "ISO1176DW" DW0016A_N 1725,3080 r180 top (schematic designator U6)
U3 "TPS7A6533QKVURQ1" KVU_1 3320,3065 r180 top
U4 "LM5017MRE/NOPB" DDA0008B_N 3435,2410 r0 top (schematic designator U1)
U5 "TPS55010RTE" RTE-16 420,1750 r90 top (schematic designator U7)
U6 "PGA11xAIPW" PW0020A_L 1690,1440 r90 top (schematic designator U5)
U7 "LM293AD" SO8 3530,1365 r90 top (schematic designator U9)
U8 "LM4041BIDBZ" SOT-23#2 2040,850 r0 top
ZZ1 "This Assembly Note is for PCB labels only" AssemblyNoteLabel 214,4459 r0 top
ZZ2 "These assemblies are ESD sensitive, ESD precautions shall be observed." AssemblyNote 215,4369 r0 top
ZZ3 "These assemblies must be clean and free from flux and all contaminants. Use of no clean flux is not acceptable." AssemblyNote 214,4278 r0 top
ZZ4 "These assemblies must comply with workmanship standards IPC-A-610 Class 2, unless otherwise specified." AssemblyNote 212,4203 r0 top

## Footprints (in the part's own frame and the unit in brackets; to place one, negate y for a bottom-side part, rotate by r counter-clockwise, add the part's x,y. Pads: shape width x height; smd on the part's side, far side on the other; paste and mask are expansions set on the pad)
0603 [mm] "0603 from SM-752 data"
  rect 1x0.95 smd: 1(-0.8,0) 2(0.8,0)
  silkscreen extent -1.52,-0.69 1.52,0.69, body extent -0.87,-0.47 0.87,0.47, height 0.85
0805_HV [mil] "0805 with 30mil clearance between pads"
  rect 50x63 smd: 1(-40,0) 2(40,0)
  silkscreen extent -74,-40 74,40, body extent -43,-29 43,29, height 43
1206 [mm] "1206 from SM-752 data"
  rect 1.3x1.85 smd: 1(-1.45,0) 2(1.45,0)
  silkscreen extent -2.4,-1.21 2.4,1.21, body extent -1.7,-0.9 1.7,0.9, height 1.35
1210 [mm] "1210 from SM-752 data"
  rect 1.3x2.7 smd: 1(-1.45,0) 2(1.45,0)
  silkscreen extent -2.32,-1.57 2.32,1.57, body extent -1.7,-1.35 1.7,1.35, height 1.35
6032-28 [mm] "Medium Density IPC based on Vishay Sprague 293D datasheet."
  rect 2.55x2.3 smd: 1(-2.375,0) 2(2.375,0)
  silkscreen extent -3.2,-2.51 3.2,1.75, body extent -3.15,-1.75 3.15,1.75, height 2.8
7343-43 [mm] "Medium density IPC based on Kemet T495 series"
  rect 2.55x2.45 smd: 1(-3.025,0) 2(3.025,0)
  silkscreen extent -4.56,-2.3 3.8,2.3, body extent -3.8,-2.3 3.8,2.3, height 4.3
760390015 [mm]
  rect 1.27x0.66 smd: 1(0,0) 2(0,-2.54) 3(0,-5.08) 4(9.14,-5.08) 5(9.14,-2.54) 6(9.14,0)
  silkscreen extent -1,-6.35 10.2,1.27, body extent -1,-6.4 10.2,1.2, height 4.2
AssemblyNote [mil] "Assembly Note"
AssemblyNoteLabel [mil] "Assembly Note for PCB Labels"
CONN_ED120-2DS [mm] "ONSHORE"
  rect 1.75x1.75 hole 1.25: 1(0,-2.54)
  round 1.75 hole 1.25: 2(0,2.54)
  silkscreen extent -5,-5.6 4,5.12, body extent -5,-5.6 4.15,5.12, height 13.1
DDA0008B_N [mm] "SOIC, 8-Leads, Body 4.9x3.9mm, Pitch 1.27mm, Exposed Pad, IPC Medium Density"
  oval 2x0.6 smd: 1(-2.5,1.905) 2(-2.5,0.635) 3(-2.5,-0.635) 4(-2.5,-1.905) 5(2.5,-1.905) 6(2.5,-0.635) 7(2.5,0.635) 8(2.5,1.905)
  rect 2.41x3.1 smd: 9(0,0)
  silkscreen extent -2.62,-2.5 1.1,2.88, body extent -2,-2.5 2,2.5, height 1.68
DO-41#1 [mil]
  rect 80x80 hole 51: 1(0,0)
  round 80 hole 51: 2(500,0)
  silkscreen extent 148,-52 352,52
DO-41#2 [mil] "diode"
  rect 68.9x68.9 hole 45.28: 1(-200,0)
  round 68.9 hole 45.28: 2(200,0)
  silkscreen extent -103,-54 102,53, body extent -217,-54 217,54, height 107
DW0016A_N [mm] "SOIC, 16-Leads, Body 10.3x7.5mm, Pitch 1.27mm, IPC Medium Density"
  oval 2.3x0.6 smd: 1(-4.55,4.445) 2(-4.55,3.175) 3(-4.55,1.905) 4(-4.55,0.635) 5(-4.55,-0.635) 6(-4.55,-1.905) 7(-4.55,-3.175) 8(-4.55,-4.445) 9(4.55,-4.445) 10(4.55,-3.175) 11(4.55,-1.905) 12(4.55,-0.635) 13(4.55,0.635) 14(4.55,1.905) 15(4.55,3.175) 16(4.55,4.445)
  silkscreen extent -4.67,-5.25 3,5.42, body extent -3.79,-5.25 3.8,5.25, height 2.64
Fiducial10-20 [mm]
  round 1 smd mask+0.5: 1(0,0)
  Top Layer keep-out circle w1.178: c0,0 r0.5
HDR100_1X2 [mil]
  rect 60x60 hole 38: 1(0,0)
  round 60 hole 38: 2(100,0)
  silkscreen extent -50,-50 150,50
HDR100_1X3 [mil]
  rect 60x60 hole 38: 1(0,0)
  round 60 hole 38: 2(100,0) 3(200,0)
  silkscreen extent -50,-50 250,50
HEADER_2X10P [mil]
  rect 60x60 hole 38: 1(0,0) 2(0,100) 3(100,0) 4(100,100) 5(200,0) 6(200,100) 7(300,0) 8(300,100) 9(400,0) 10(400,100) 11(500,0) 12(500,100) 13(600,0) 14(600,100) 15(700,0) 16(700,100) 17(800,0) 18(800,100) 19(900,0) 20(900,100)
  silkscreen extent -50,-50 950,150
HEATSINK_513201 [mil]
  round 166 hole 106.5: 1(-500,0) 2(500,0)
IND_0805-4P [mil]
  rect 40x20 smd: 1(-35,-15) 2(35,-15) 3(35,15) 4(-35,15)
Keystone_1902C [mil] "Hex Standoff, 4-40 threaded, nylon"
  body extent -145,-126 146,126, height 501
KVU_1 [mm]
  rect 1.2x2.8 smd: 1(-2.29,-3.635) 3(2.29,-3.635)
  rect 6.096x6.096 smd: 2(0,3.635)
  silkscreen extent -3.43,-7.16 3.43,7.22
Label_650x200 [mil] "Thermal Transfer Label"
  silkscreen extent -325,-100 325,100, body extent -326,-101 326,101, height 1
LED0603AA [mil]
  rect 32x32 smd: 1(-32.48,0) 2(32.48,0)
  silkscreen extent -132,-25 11,25
MF03A_N [mm] "SOT23, 3-Leads, Body 2.9x1.3mm, Pitch 0.95mm, Lead Span 2.4mm, IPC Medium Density"
  rect 1.3x0.6 smd: 1(-1.05,0.95) 2(-1.05,-0.95) 3(1.05,0)
  silkscreen extent -1.17,-1.5 0.7,1.93, body extent -0.7,-1.5 0.7,1.5, height 1.12
MH3.2_H5_W6_KO8_STARHEAD [mil]
  round 20 / inner round 142 / far side round 20 hole 128 unplated mask+64: 1(0,0)
  Keep-Out Layer region: 160,0 147.82,61.23 113.14,113.14 61.23,147.82 0,160 0,160 -61.23,147.82 -113.14,113.14 -147.82,61.23 -160,0 -160,0 -147.82,-61.23 -113.14,-113.14 -61.23,-147.82 0,-160 0,-160 61.23,-147.82 113.14,-113.14 147.82,-61.23 160,0
  silkscreen extent -120,-120 120,120
"NY PMS 440 0025 PH" [mm] "4-40 nylon screw and mounting hole"
  round 8 hole 3.2: 1(0,0)
  body extent -3.3,-3.3 3.3,3.3, height 2.69
PW0020A_L [mm] "TSOP, 20-Leads, Body 6.5x4.4mm, Pitch 0.65mm, IPC High Density"
  oval 1.4x0.35 smd: 1(-2.8,2.925) 2(-2.8,2.275) 3(-2.8,1.625) 4(-2.8,0.975) 5(-2.8,0.325) 6(-2.8,-0.325) 7(-2.8,-0.975) 8(-2.8,-1.625) 9(-2.8,-2.275) 10(-2.8,-2.925) 11(2.8,-2.925) 12(2.8,-2.275) 13(2.8,-1.625) 14(2.8,-0.975) 15(2.8,-0.325) 16(2.8,0.325) 17(2.8,0.975) 18(2.8,1.625) 19(2.8,2.275) 20(2.8,2.925)
  silkscreen extent -2.92,-3.3 1.7,3.77, body extent -2.25,-3.3 2.25,3.3, height 1.2
RTE-16 [mil]
  rect 32.24x11.8 smd mask+1: 1(-59.45,29.55) 2(-59.45,9.85) 3(-59.45,-9.85) 4(-59.45,-29.55) 9(59.55,-29.55) 10(59.55,-9.85) 11(59.55,9.85) 12(59.55,29.55)
  rect 11.8x32.24 smd mask+1: 5(-29.5,-59.5) 6(-9.8,-59.5) 7(9.9,-59.5) 8(29.6,-59.5) 13(29.6,59.5) 14(9.9,59.5) 15(-9.8,59.5) 16(-29.5,59.5)
  rect 57.09x57.09 smd mask+1.18: 17(0.15,-0.05)
  silkscreen extent -128,32 -98,62
SMA [mm] "Molded Diode, 2-Leads, Body 4.3x2.6mm, IPC Medium Density, based on OnSemi component dimensions and land pattern"
  rect 2x2 smd: 1(-2,0) 2(2,0)
  silkscreen extent -3.66,-1.57 2.79,1.57, body extent -2.6,-1.3 2.6,1.3, height 2.42
SMB [mil] "Molded Diode, 2-Leads, Body 5.4x3.6mm, IPC Medium Density, based on OnSemi component dimensions"
  rect 85x107.99 smd: 1(-87.01,0) 2(87.01,0)
  silkscreen extent -155,-82 125,82, body extent -106,-71 106,71, height 91
SMC [mil] "Molded Diode, 2-Leads, Body 6.9x5.8mm, IPC Medium Density, based on OnSemi component dimensions and land patterns"
  rect 110x150 smd: 1(-140.49,0) 2(140.49,0)
  silkscreen extent -221,-124 189,124, body extent -156,-116 156,116, height 91
SO8 [mil]
  rect 80x26 smd: 1(-95,75) 2(-95,25) 3(-95,-25) 4(-95,-75) 5(94,-75) 6(94,-25) 7(94,25) 8(94,75)
  silkscreen extent -200,100 -160,140
SON_CSD17571Q2 [mm] "SON, MOSFET, N-CH, 30V, 22A, SON 2X2 MM"
  rect 0.4x0.455 smd mask+0.032: 1(-0.65,-0.923) 2(0,-0.923) 3(0.65,-0.923) 4(0.65,0.923) 5(0,0.923) 6(-0.65,0.923)
  rect 0.4x0.85 smd mask+0.038: 7(0.65,0.096)
  rect 1.05x1.1 smd mask+0.032: 8(-0.325,0)
  silkscreen extent -1.1,-2.07 1.1,1, body extent -1,-1 1,0.97, height 0.85
SOT-23#1 [mm] "SOT23, 3-Leads, Body 2.9x1.3mm, Pitch 0.95mm, Lead Span 2.5mm, IPC Medium Density"
  rect 1.5x0.6 smd: 1(-0.95,0.95) 2(-0.95,-0.95) 3(0.95,0)
  silkscreen extent 0.2,-1.5 0.7,1.5, body extent -1.16,-1.45 1.21,1.45, height 1
SOT-23#2 [mm]
  rect 0.889x0.889 smd: 1(-0.953,-1.333) 2(0.953,-1.333) 3(0,1.27)
SRR7045 [mm] "BOURNS"
  rect 1.8x2.4 smd: 1(-3,0) 2(3,0)
  silkscreen extent -3.7,-3.7 3.7,3.7, body extent -3.65,-3.65 3.65,3.65, height 4.8
TB_3X5.1MM [mil]
  rect 100x100 hole 52: 1(0,0) 2(200,0) 3(400,0)
TI_Stacked_SolderMask_Small [mil]
  silkscreen extent -418,-98 418,98
TO-220AB [mil] "Copied from Altium's version of TO3B"
  rect 76x118.11 hole 50: 1(-100,0)
  oval 76x118.11 hole 50: 2(0,0) 3(100,0)
  silkscreen extent -225,-73 225,130, body extent -221,-59 221,126, height 765
TP-040_RND [mil]
  round 70 / inner round 62 / far side round 62 hole 40: 1(0,0)
YXJ_1000x2000 [mm] "RUBYCON"
  rect 1.7x1.7 hole 0.914: 1(-2.5,0)
  round 1.7 hole 0.914: 2(2.5,0)
  silkscreen extent -5.3,-5.3 5.3,5.3, body extent -5.21,-5.24 5.24,5.24, height 22.01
